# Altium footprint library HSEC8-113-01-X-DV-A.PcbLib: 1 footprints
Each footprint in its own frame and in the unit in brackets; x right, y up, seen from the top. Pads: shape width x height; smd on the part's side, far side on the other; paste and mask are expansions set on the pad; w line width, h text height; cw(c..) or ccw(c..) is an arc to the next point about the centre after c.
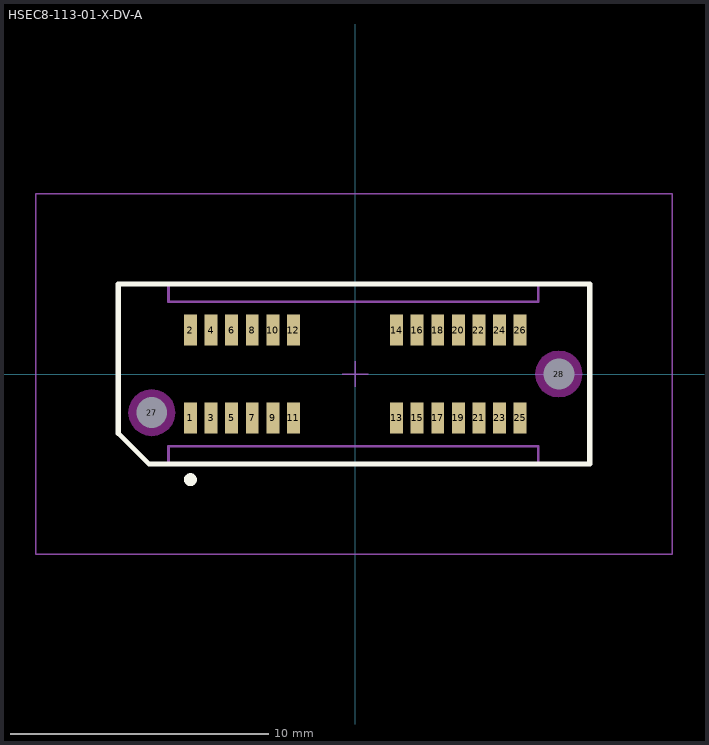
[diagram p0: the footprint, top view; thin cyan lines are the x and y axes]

## HSEC8-113-01-X-DV-A [mm] "0.80mm pitch, 26 pin, hi-speed micro edge card; w/alignment pins"
height 7.98
pads (28):
  rect 0.5x1.2 smd mask+0: 1(-6.4,-1.7) 2(-6.4,1.7) 3(-5.6,-1.7) 4(-5.6,1.7) 5(-4.8,-1.7) 6(-4.8,1.7) 7(-4,-1.7) 8(-4,1.7) 9(-3.2,-1.7) 10(-3.2,1.7) 11(-2.4,-1.7) 12(-2.4,1.7) 13(1.6,-1.7) 14(1.6,1.7) 15(2.4,-1.7) 16(2.4,1.7) 17(3.2,-1.7) 18(3.2,1.7) 19(4,-1.7) 20(4,1.7) 21(4.8,-1.7) 22(4.8,1.7) 23(5.6,-1.7) 24(5.6,1.7) 25(6.4,-1.7) 26(6.4,1.7)
  round 0.5 hole 1.2 unplated mask+0: 27(-7.9,-1.5) 28(7.9,0)
Top Overlay:
  circle w0.25: c-6.4,-4.1 r0.125
  lines w0.2: -9.2,-2.3 -8,-3.5 9.1,-3.5 9.1,3.5 -9.2,3.5 -9.2,-2.3
Keep-Out Layer:
  pour cut-out: -6.992,-1.5 -7.023,-1.265 -7.114,-1.046 -7.258,-0.858 -7.446,-0.714 -7.665,-0.623 -7.9,-0.592 -8.135,-0.623 -8.354,-0.714 -8.542,-0.858 -8.686,-1.046 -8.777,-1.265 -8.808,-1.5 -8.777,-1.735 -8.686,-1.954 -8.542,-2.142 -8.354,-2.286 -8.135,-2.377 -7.9,-2.408 -7.665,-2.377 -7.446,-2.286 -7.258,-2.142 -7.114,-1.954 -7.023,-1.735
  pour cut-out: 8.808,0 8.777,0.235 8.686,0.454 8.542,0.642 8.354,0.786 8.135,0.877 7.9,0.908 7.665,0.877 7.446,0.786 7.258,0.642 7.114,0.454 7.023,0.235 6.992,0 7.023,-0.235 7.114,-0.454 7.258,-0.642 7.446,-0.786 7.665,-0.877 7.9,-0.908 8.135,-0.877 8.354,-0.786 8.542,-0.642 8.686,-0.454 8.777,-0.235
Mechanical 13:
  lines w0.1: -9.2,-2.3 -8,-3.5 -7.25,-3.5 -7.25,-2.8 7.1,-2.8 7.1,-3.5 9.1,-3.5 9.1,3.5 7.1,3.5 7.1,2.8 -7.25,2.8 -7.25,3.5 -9.2,3.5 -9.2,-2.3
  text ".Designator" at 0,0 h1.52
Mechanical 15:
  lines w0.05: -0.5,0 0.5,0 ; 0,-0.5 0,0.5 ; -12.4,-7 12.3,-7 12.3,7 -12.4,7 -12.4,-7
